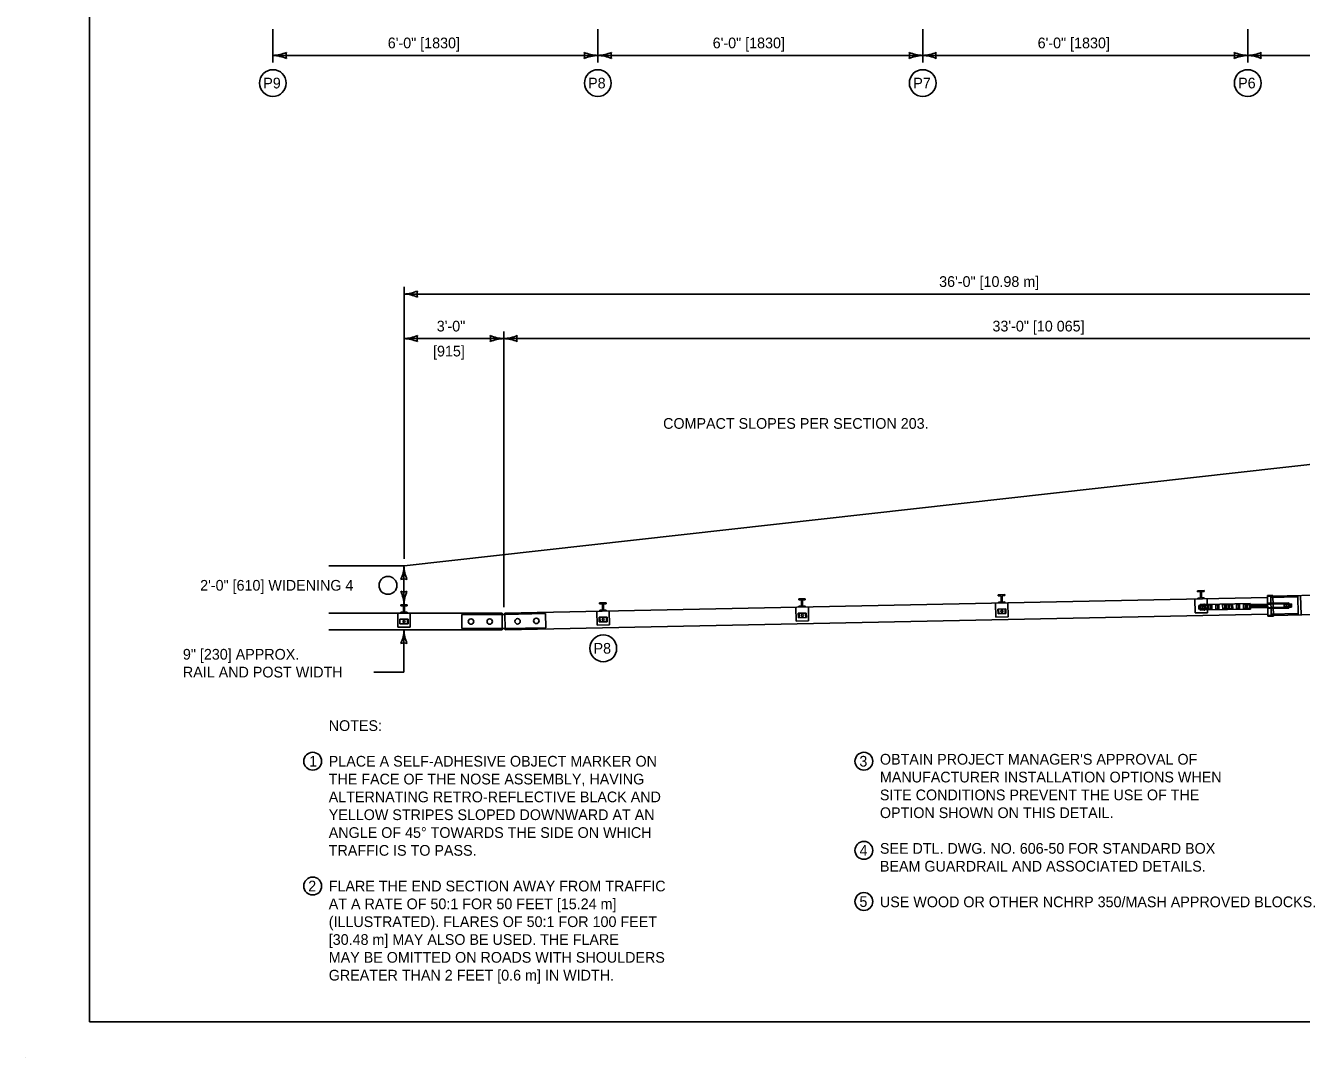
# Model space of a CAD drawing. Extents: x 49991.4 to 50021, y 49987.6 to 50011.4.
# Drawn here: x 49999.02 to 50006.18, y 49987.6 to 49993.39 of the extents above; entities that cross this region are included whole.
import ezdxf

# ---------------------------------------------------------------- set-up
doc = ezdxf.new("R2010")
doc.units = 0
for name, color, linetype in [('Level 1', 7, 'Continuous'), ('Level 2', 7, 'Continuous'), ('Level 3', 7, 'Continuous'), ('Level 4', 7, 'Continuous')]:
    doc.layers.add(name, color=color, linetype=linetype)

msp = doc.modelspace()

# ---------------------------------------------------------------- linework, layer by layer
at = {"layer": 'Level 1'}
for p, q in [((50007.8759, 49991.1095), (50001.1481, 49990.3564)), ((50001.1481, 49990.3564), (50000.7259, 49990.3564)), ((50010.3716, 49990.2756), (50006.023, 49990.1867)), ((50004.5183, 49990.1948), (50004.4821, 49990.1941)), ((50004.4821, 49990.1885), (50004.4821, 49990.1941)), ((50004.5184, 49990.1892), (50004.5183, 49990.1948)), ((50005.6363, 49990.2177), (50005.6001, 49990.217)), ((50005.6002, 49990.2114), (50005.6001, 49990.217)), ((50005.6155, 49990.2116), (50005.6002, 49990.2114)), ((50005.6162, 49990.1763), (50005.6155, 49990.2116)), ((50005.6364, 49990.2121), (50005.6211, 49990.2118)), ((50005.6218, 49990.1764), (50005.6211, 49990.2118)), ((50005.6364, 49990.2121), (50005.6363, 49990.2177)), ((50001.13, 49990.1317), (50001.13, 49990.1374)), ((50001.1662, 49990.1374), (50001.13, 49990.1374)), ((50001.1453, 49990.1317), (50001.13, 49990.1317)), ((50001.1453, 49990.0964), (50001.1453, 49990.1317)), ((50001.151, 49990.0964), (50001.151, 49990.1317)), ((50001.1662, 49990.1317), (50001.151, 49990.1317)), ((50001.1662, 49990.1317), (50001.1662, 49990.1374)), ((50005.992, 49990.1783), (50001.7142, 49990.0907)), ((50002.2817, 49990.149), (50002.2455, 49990.1483)), ((50002.2455, 49990.1426), (50002.2455, 49990.1483)), ((50002.2609, 49990.1429), (50002.2455, 49990.1426)), ((50002.2617, 49990.1076), (50002.2609, 49990.1429)), ((50002.2819, 49990.1433), (50002.2666, 49990.143)), ((50002.2673, 49990.1077), (50002.2666, 49990.143)), ((50002.2819, 49990.1433), (50002.2817, 49990.149)), ((50003.3986, 49990.1718), (50003.3623, 49990.1711)), ((50003.3624, 49990.1655), (50003.3623, 49990.1711)), ((50003.3778, 49990.1658), (50003.3624, 49990.1655)), ((50003.3785, 49990.1304), (50003.3631, 49990.1301)), ((50003.3632, 49990.1245), (50003.3631, 49990.1301)), ((50003.3785, 49990.1304), (50003.3778, 49990.1658)), ((50003.3987, 49990.1662), (50003.3833, 49990.1659)), ((50003.384, 49990.1305), (50003.3833, 49990.1659)), ((50003.3994, 49990.1308), (50003.384, 49990.1305)), ((50003.3987, 49990.1662), (50003.3986, 49990.1718)), ((50003.3995, 49990.1252), (50003.3994, 49990.1308)), ((50004.4974, 49990.1887), (50004.4821, 49990.1885)), ((50004.4982, 49990.1533), (50004.4829, 49990.153)), ((50004.4831, 49990.1474), (50004.4829, 49990.153)), ((50004.4982, 49990.1533), (50004.4974, 49990.1887)), ((50004.5184, 49990.1892), (50004.503, 49990.1888)), ((50004.5038, 49990.1535), (50004.503, 49990.1888)), ((50004.5191, 49990.1538), (50004.5038, 49990.1535)), ((50004.5192, 49990.1482), (50004.5191, 49990.1538)), ((50005.6162, 49990.1763), (50005.6009, 49990.1759)), ((50005.6011, 49990.1703), (50005.6009, 49990.1759)), ((50005.6371, 49990.1767), (50005.6218, 49990.1764)), ((50005.6372, 49990.1711), (50005.6371, 49990.1767)), ((50006.0229, 49990.1907), (50005.9918, 49990.1901)), ((50005.9942, 49990.0736), (50005.9918, 49990.1901)), ((50006.0253, 49990.0742), (50006.0229, 49990.1907)), ((50001.6988, 49990.0908), (50000.7259, 49990.0908)), ((50001.1249, 49990.0578), (50001.1249, 49990.0306)), ((50001.1714, 49990.0578), (50001.1249, 49990.0578)), ((50001.1453, 49990.0964), (50001.13, 49990.0964)), ((50001.13, 49990.0908), (50001.13, 49990.0964)), ((50001.1662, 49990.0964), (50001.151, 49990.0964)), ((50001.1662, 49990.0908), (50001.1662, 49990.0964)), ((50001.1677, 49990.0578), (50001.1677, 49990.0306)), ((50001.1714, 49990.0578), (50001.1714, 49990.0306)), ((50001.6988, 49990.0907), (50001.6988, 49989.9976)), ((50001.7143, 49990.0838), (50001.6988, 49990.0838)), ((50001.7142, 49990.0907), (50001.7161, 49989.9975)), ((50002.243, 49990.0679), (50002.2878, 49990.0688)), ((50002.2878, 49990.0688), (50002.243, 49990.0679)), ((50002.2435, 49990.0421), (50002.243, 49990.0679)), ((50002.2435, 49990.0421), (50002.243, 49990.0679)), ((50002.2617, 49990.1076), (50002.2463, 49990.1072)), ((50002.2464, 49990.1016), (50002.2463, 49990.1072)), ((50002.2837, 49990.0688), (50002.2471, 49990.068)), ((50002.2471, 49990.068), (50002.2476, 49990.0422)), ((50002.2471, 49990.068), (50002.2476, 49990.0422)), ((50002.2826, 49990.1081), (50002.2673, 49990.1077)), ((50002.2827, 49990.1025), (50002.2826, 49990.1081)), ((50002.2842, 49990.0429), (50002.2837, 49990.0688)), ((50002.2842, 49990.0429), (50002.2837, 49990.0688)), ((50002.2878, 49990.0688), (50002.2883, 49990.043)), ((50002.2883, 49990.043), (50002.2878, 49990.0688)), ((50003.3601, 49990.0908), (50003.4049, 49990.0917)), ((50003.3606, 49990.0649), (50003.3601, 49990.0908)), ((50003.3606, 49990.0649), (50003.4054, 49990.0658)), ((50003.3642, 49990.0908), (50003.3647, 49990.065)), ((50003.4008, 49990.0916), (50003.4013, 49990.0657)), ((50003.4054, 49990.0658), (50003.4049, 49990.0917)), ((50004.4798, 49990.1137), (50004.5246, 49990.1146)), ((50004.4804, 49990.0879), (50004.4798, 49990.1137)), ((50004.4804, 49990.0879), (50004.5251, 49990.0888)), ((50004.4839, 49990.1138), (50004.4844, 49990.088)), ((50004.5205, 49990.1145), (50004.521, 49990.0887)), ((50004.5251, 49990.0888), (50004.5246, 49990.1146)), ((50006.0253, 49990.0742), (50005.9942, 49990.0736)), ((50006.7216, 49990.0924), (50006.0252, 49990.078)), ((50001.6988, 49989.9976), (50000.7259, 49989.9976)), ((50001.1714, 49990.0306), (50001.1249, 49990.0306)), ((50001.716, 49990.0044), (50001.6988, 49990.0044)), ((50002.2883, 49990.043), (50002.2435, 49990.0421)), ((50002.2435, 49990.0421), (50002.2883, 49990.043)), ((49999.0245, 49987.5988), (49999.0245, 49987.5988))]:
    msp.add_line(p, q, dxfattribs=at)
msp.add_lwpolyline([(49999.3835, 49998.9992), (50016.7501, 49998.9992), (50016.7501, 49987.7988), (49999.3835, 49987.7988)], close=True, dxfattribs=at)
msp.add_lwpolyline([(50001.7161, 49989.9975), (50005.994, 49990.0852)], dxfattribs=at)
for centre, radius in [((50001.1482, 49990.0442), 0.00582), ((50001.524, 49990.0441), 0.0153), ((50001.6288, 49990.0441), 0.0153), ((50001.7852, 49990.0455), 0.0153), ((50001.89, 49990.0477), 0.0153), ((50002.2656, 49990.0555), 0.00582), ((50003.3827, 49990.0783), 0.00582), ((50004.5025, 49990.1012), 0.00582)]:
    msp.add_circle(centre, radius, dxfattribs=at)
at = {"layer": 'Level 2'}
for centre, radius in [((50000.4122, 49993.0644), 0.075), ((50002.2352, 49993.0644), 0.075), ((50004.0582, 49993.0644), 0.075), ((50005.8814, 49993.0644), 0.075), ((50001.0578, 49990.2469), 0.05), ((50002.2658, 49989.8938), 0.075), ((50000.6357, 49989.2604), 0.05), ((50003.7279, 49989.2604), 0.05), ((50003.7279, 49988.7604), 0.05), ((50000.6357, 49988.5604), 0.05), ((50003.7279, 49988.4735), 0.05)]:
    msp.add_circle(centre, radius, dxfattribs=at)
at = {"layer": 'Level 3'}
for p, q in [((50000.4122, 49993.3671), (50000.4122, 49993.1794)), ((50002.2352, 49993.3671), (50002.2352, 49993.1794)), ((50004.0582, 49993.3671), (50004.0582, 49993.1794)), ((50005.8814, 49993.3671), (50005.8814, 49993.1794)), ((50002.2358, 49993.2194), (50000.4128, 49993.2194)), ((50004.0588, 49993.2194), (50002.2358, 49993.2194)), ((50005.8818, 49993.2194), (50004.0588, 49993.2194)), ((50007.7048, 49993.2194), (50005.8818, 49993.2194)), ((50001.1481, 49990.3964), (50001.1481, 49991.921)), ((50007.8759, 49991.881), (50001.1481, 49991.881)), ((50001.7075, 49991.631), (50001.1481, 49991.631)), ((50001.7075, 49990.1238), (50001.7075, 49991.671)), ((50007.8759, 49991.631), (50001.7075, 49991.631)), ((50001.1478, 49990.1374), (50001.1478, 49990.3564)), ((50001.1478, 49989.7604), (50001.1478, 49989.9976)), ((50000.978, 49989.7604), (50001.1478, 49989.7604))]:
    msp.add_line(p, q, dxfattribs=at)
for centre, radius, start, end in [((50000.4007, 49993.4521), 0.233, 272.82731, 292.07716), ((50000.403, 49992.9972), 0.2223, 67.45601, 87.63952), ((50000.5404, 49993.2194), 0.0548, 162.13882, 197.86118), ((50002.2444, 49993.4415), 0.2223, 247.45601, 267.63952), ((50002.107, 49993.2194), 0.0548, 342.13882, 17.86118), ((50002.2467, 49992.9867), 0.233, 92.82731, 112.07716), ((50002.2237, 49993.4521), 0.233, 272.82731, 292.07716), ((50002.226, 49992.9973), 0.2223, 67.45601, 87.63952), ((50002.3634, 49993.2194), 0.0548, 162.13882, 197.86118), ((50004.0674, 49993.4415), 0.2223, 247.45601, 267.63952), ((50003.93, 49993.2194), 0.0548, 342.13882, 17.86118), ((50004.0697, 49992.9867), 0.233, 92.82731, 112.07716), ((50004.0467, 49993.4521), 0.233, 272.82731, 292.07716), ((50004.049, 49992.9973), 0.2223, 67.45601, 87.63952), ((50004.1864, 49993.2194), 0.0548, 162.13882, 197.86118), ((50005.8906, 49993.4415), 0.2223, 247.45601, 267.63952), ((50005.7532, 49993.2194), 0.0548, 342.13882, 17.86118), ((50005.8929, 49992.9867), 0.233, 92.82731, 112.07716), ((50005.8699, 49993.4521), 0.233, 272.82731, 292.07716), ((50005.8722, 49992.9973), 0.2223, 67.45601, 87.63952), ((50006.0096, 49993.2194), 0.0548, 162.13882, 197.86118), ((50001.1366, 49992.1137), 0.233, 272.82731, 292.07716), ((50001.1389, 49991.6589), 0.2223, 67.45601, 87.63952), ((50001.2763, 49991.881), 0.0548, 162.13882, 197.86118), ((50001.1366, 49991.8637), 0.233, 272.82731, 292.07716), ((50001.1389, 49991.4089), 0.2223, 67.45601, 87.63952), ((50001.2763, 49991.631), 0.0548, 162.13882, 197.86118), ((50001.7167, 49991.8531), 0.2223, 247.45601, 267.63952), ((50001.5793, 49991.631), 0.0548, 342.13882, 17.86118), ((50001.719, 49991.3983), 0.233, 92.82731, 112.07716), ((50001.696, 49991.8637), 0.233, 272.82731, 292.07716), ((50001.6983, 49991.4089), 0.2223, 67.45601, 87.63952), ((50001.8357, 49991.631), 0.0548, 162.13882, 197.86118), ((50000.9257, 49990.3656), 0.2223, 337.45601, 357.63952), ((50001.3805, 49990.3679), 0.233, 182.82731, 202.07716), ((50001.1478, 49990.2282), 0.0548, 72.13882, 107.86118), ((50001.1478, 49990.2656), 0.0548, 252.13882, 287.86118), ((50000.9151, 49990.1259), 0.233, 2.82731, 22.07716), ((50001.3699, 49990.1282), 0.2223, 157.45601, 177.63952), ((50000.9257, 49990.0068), 0.2223, 337.45601, 357.63952), ((50001.3805, 49990.0091), 0.233, 182.82731, 202.07716), ((50001.1478, 49989.8694), 0.0548, 72.13882, 107.86118)]:
    msp.add_arc(centre, radius, start, end, dxfattribs=at)
at = {"layer": 'Level 4'}
for p, q in [((50003.348, 49990.0465), (50003.3465, 49990.1241)), ((50003.4181, 49990.0479), (50003.4164, 49990.1255)), ((50004.4677, 49990.0694), (50004.4661, 49990.1471)), ((50004.5376, 49990.0708), (50004.536, 49990.1485)), ((50005.5857, 49990.0923), (50005.5842, 49990.17)), ((50005.6062, 49990.1335), (50005.6396, 49990.1341)), ((50005.6066, 49990.1142), (50005.6062, 49990.1335)), ((50005.6105, 49990.1197), (50005.6103, 49990.128)), ((50005.6138, 49990.1396), (50005.6356, 49990.14)), ((50005.6145, 49990.1085), (50005.6138, 49990.1396)), ((50005.614, 49990.1312), (50005.6358, 49990.1316)), ((50005.6254, 49990.1088), (50005.6248, 49990.1398)), ((50005.6394, 49990.142), (50005.6356, 49990.142)), ((50005.6363, 49990.1071), (50005.6356, 49990.142)), ((50005.8956, 49990.1453), (50005.6394, 49990.14)), ((50005.6401, 49990.1071), (50005.6394, 49990.142)), ((50005.6569, 49990.1366), (50005.6453, 49990.1364)), ((50005.6459, 49990.113), (50005.6453, 49990.1364)), ((50005.6558, 49990.0937), (50005.6541, 49990.1714)), ((50005.6575, 49990.1133), (50005.6569, 49990.1366)), ((50005.6803, 49990.137), (50005.6628, 49990.1367)), ((50005.6633, 49990.1134), (50005.6628, 49990.1367)), ((50005.6748, 49990.1137), (50005.6744, 49990.1369)), ((50005.6807, 49990.1138), (50005.6803, 49990.137)), ((50005.719, 49990.1379), (50005.7015, 49990.1375)), ((50005.702, 49990.1143), (50005.7015, 49990.1375)), ((50005.7137, 49990.1145), (50005.7132, 49990.1378)), ((50005.7195, 49990.1146), (50005.719, 49990.1379)), ((50005.758, 49990.1387), (50005.7405, 49990.1383)), ((50005.741, 49990.115), (50005.7405, 49990.1383)), ((50005.7526, 49990.1152), (50005.7521, 49990.1386)), ((50005.7585, 49990.1153), (50005.758, 49990.1387)), ((50005.7735, 49990.139), (50005.7619, 49990.1388)), ((50005.7624, 49990.1155), (50005.7619, 49990.1388)), ((50005.774, 49990.1157), (50005.7735, 49990.139)), ((50005.7968, 49990.1393), (50005.7793, 49990.1391)), ((50005.7798, 49990.1158), (50005.7793, 49990.1391)), ((50005.7914, 49990.1161), (50005.791, 49990.1392)), ((50005.7972, 49990.1162), (50005.7968, 49990.1393)), ((50005.8355, 49990.1402), (50005.818, 49990.1399)), ((50005.8185, 49990.1166), (50005.818, 49990.1399)), ((50005.8301, 49990.1168), (50005.8296, 49990.1401)), ((50005.836, 49990.1169), (50005.8355, 49990.1402)), ((50005.8743, 49990.141), (50005.8569, 49990.1407)), ((50005.8574, 49990.1174), (50005.8569, 49990.1407)), ((50005.8689, 49990.1175), (50005.8685, 49990.1409)), ((50005.8748, 49990.1176), (50005.8743, 49990.141)), ((50005.8899, 49990.1413), (50005.8783, 49990.1412)), ((50005.8787, 49990.1179), (50005.8783, 49990.1412)), ((50005.8905, 49990.1181), (50005.8899, 49990.1413)), ((50005.8963, 49990.1143), (50005.8956, 49990.1453)), ((50005.8957, 49990.1395), (50006.1271, 49990.1442)), ((50006.1275, 49990.1248), (50005.8962, 49990.1201)), ((50005.8999, 49990.1258), (50005.8998, 49990.134)), ((50005.9039, 49990.1202), (50005.9034, 49990.1396)), ((50005.9077, 49990.1258), (50005.9076, 49990.1341)), ((50005.9117, 49990.1205), (50005.9112, 49990.1398)), ((50005.9154, 49990.1261), (50005.9153, 49990.1343)), ((50005.9194, 49990.1206), (50005.919, 49990.14)), ((50005.9231, 49990.1262), (50005.923, 49990.1344)), ((50005.9273, 49990.1207), (50005.9269, 49990.1401)), ((50005.9311, 49990.1263), (50005.931, 49990.1346)), ((50005.935, 49990.1209), (50005.9346, 49990.1403)), ((50005.9388, 49990.1266), (50005.9387, 49990.1348)), ((50005.9427, 49990.1211), (50005.9423, 49990.1404)), ((50005.9466, 49990.1266), (50005.9464, 49990.1349)), ((50005.9505, 49990.1212), (50005.9501, 49990.1406)), ((50005.9544, 49990.1268), (50005.9541, 49990.1351)), ((50005.9583, 49990.1214), (50005.958, 49990.1408)), ((50005.9622, 49990.1271), (50005.9619, 49990.1353)), ((50005.966, 49990.1215), (50005.9657, 49990.1409)), ((50005.9699, 49990.1272), (50005.9696, 49990.1354)), ((50005.9738, 49990.1217), (50005.9735, 49990.141)), ((50005.9778, 49990.1273), (50005.9775, 49990.1355)), ((50005.9816, 49990.1219), (50005.9813, 49990.1413)), ((50005.9855, 49990.1274), (50005.9853, 49990.1357)), ((50005.9895, 49990.122), (50005.9892, 49990.1414)), ((50006.023, 49990.1867), (50005.9919, 49990.1861)), ((50005.9927, 49990.1474), (50006.1115, 49990.1497)), ((50006.0137, 49990.0779), (50006.0115, 49990.1864)), ((50006.1629, 49990.1819), (50006.0117, 49990.1786)), ((50006.0864, 49990.1183), (50006.0858, 49990.1492)), ((50006.0904, 49990.1183), (50006.0898, 49990.1493)), ((50006.09, 49990.1408), (50006.1117, 49990.1412)), ((50006.1119, 49990.1272), (50006.0902, 49990.1266)), ((50006.1012, 49990.1186), (50006.1006, 49990.1495)), ((50006.1121, 49990.1188), (50006.1115, 49990.1497)), ((50006.1156, 49990.1302), (50006.1154, 49990.1384)), ((50006.1198, 49990.1246), (50006.1195, 49990.144)), ((50006.1236, 49990.1302), (50006.1234, 49990.1385)), ((50006.1275, 49990.1248), (50006.1271, 49990.1442)), ((50006.165, 49990.0809), (50006.1627, 49990.1896)), ((50006.1806, 49990.0812), (50006.1783, 49990.1899)), ((50001.1131, 49990.013), (50001.1131, 49990.0908)), ((50001.183, 49990.013), (50001.183, 49990.0908)), ((50001.4715, 49990.0044), (50001.4715, 49990.0838)), ((50001.4715, 49990.0838), (50001.6988, 49990.0838)), ((50001.9416, 49990.0885), (50001.7143, 49990.0838)), ((50001.9432, 49990.009), (50001.9416, 49990.0885)), ((50002.2312, 49990.0235), (50002.2295, 49990.1013)), ((50002.301, 49990.0249), (50002.2995, 49990.1028)), ((50004.5376, 49990.0708), (50004.4677, 49990.0694)), ((50005.6558, 49990.0937), (50005.5857, 49990.0923)), ((50005.6399, 49990.1147), (50005.6066, 49990.1141)), ((50005.6361, 49990.1174), (50005.6143, 49990.1169)), ((50005.6362, 49990.109), (50005.6145, 49990.1085)), ((50005.6401, 49990.1071), (50005.6363, 49990.1071)), ((50005.8963, 49990.1143), (50005.64, 49990.1091)), ((50005.6575, 49990.1133), (50005.6459, 49990.113)), ((50005.6807, 49990.1138), (50005.6633, 49990.1134)), ((50005.7195, 49990.1146), (50005.702, 49990.1143)), ((50005.7585, 49990.1153), (50005.741, 49990.115)), ((50005.774, 49990.1157), (50005.7624, 49990.1155)), ((50005.7972, 49990.1162), (50005.7798, 49990.1158)), ((50005.836, 49990.1169), (50005.8185, 49990.1166)), ((50005.8748, 49990.1176), (50005.8574, 49990.1174)), ((50005.8905, 49990.1181), (50005.8787, 49990.1179)), ((50006.1121, 49990.1188), (50005.9933, 49990.1163)), ((50006.0252, 49990.078), (50005.9941, 49990.0775)), ((50006.1648, 49990.0888), (50006.0135, 49990.0856)), ((50001.183, 49990.013), (50001.1131, 49990.013)), ((50001.4715, 49990.0044), (50001.6988, 49990.0044)), ((50001.9432, 49990.009), (50001.716, 49990.0044)), ((50002.301, 49990.0249), (50002.2312, 49990.0235)), ((50003.4181, 49990.0479), (50003.348, 49990.0465))]:
    msp.add_line(p, q, dxfattribs=at)

# ---------------------------------------------------------------- texts
at = {"layer": 'Level 1'}
msp.add_text('6\'-0" [1830]', height=0.06, dxfattribs=at).set_placement((50001.0568, 49993.2594))
at = {"layer": 'Level 2'}
for s, p in [('6\'-0" [1830]', (50002.8798, 49993.2594)), ('6\'-0" [1830]', (50004.7028, 49993.2594)), ('P9', (50000.3583, 49993.0344)), ('P8', (50002.1808, 49993.0344)), ('P7', (50004.005, 49993.0344)), ('P6', (50005.8275, 49993.0344)), ('36\'-0" [10.98 m]', (50004.1502, 49991.921)), ('3\'-0"', (50001.3317, 49991.671)), ('33\'-0" [10 065]', (50004.4493, 49991.671)), ('[915]', (50001.3107, 49991.531)), ('COMPACT SLOPES PER SECTION 203.', (50002.6016, 49991.1251)), ('2\'-0" [610] WIDENING 4', (50000.0042, 49990.2172)), ('P8', (50002.2114, 49989.8638)), ('9" [230] APPROX.', (49999.9075, 49989.8304)), ('RAIL AND POST WIDTH', (49999.9075, 49989.7304)), ('NOTES:', (50000.7257, 49989.4304)), ('1', (50000.6159, 49989.2304)), ('PLACE A SELF-ADHESIVE OBJECT MARKER ON', (50000.7257, 49989.2304)), ('3', (50003.7027, 49989.2304)), ("OBTAIN PROJECT MANAGER'S APPROVAL OF ", (50003.8179, 49989.2416)), ('THE FACE OF THE NOSE ASSEMBLY, HAVING', (50000.7257, 49989.1304)), ('MANUFACTURER INSTALLATION OPTIONS WHEN ', (50003.8179, 49989.1416)), ('ALTERNATING RETRO-REFLECTIVE BLACK AND', (50000.7257, 49989.0304)), ('SITE CONDITIONS PREVENT THE USE OF THE ', (50003.8179, 49989.0416)), ('YELLOW STRIPES SLOPED DOWNWARD AT AN', (50000.7257, 49988.9304)), ('OPTION SHOWN ON THIS DETAIL.', (50003.8179, 49988.9416)), ('ANGLE OF 45° TOWARDS THE SIDE ON WHICH', (50000.7257, 49988.8304)), ('TRAFFIC IS TO PASS.', (50000.7257, 49988.7304)), ('4', (50003.7039, 49988.7304)), ('SEE DTL. DWG. NO. 606-50 FOR STANDARD BOX ', (50003.8179, 49988.7416)), ('BEAM GUARDRAIL AND ASSOCIATED DETAILS.', (50003.8179, 49988.6416)), ('2', (50000.6105, 49988.5304)), ('FLARE THE END SECTION AWAY FROM TRAFFIC', (50000.7257, 49988.5304)), ('AT A RATE OF 50:1 FOR 50 FEET [15.24 m]', (50000.7257, 49988.4304)), ('5', (50003.703, 49988.4435)), ('USE WOOD OR OTHER NCHRP 350/MASH APPROVED BLOCKS.', (50003.8179, 49988.4416)), ('(ILLUSTRATED). FLARES OF 50:1 FOR 100 FEET', (50000.7257, 49988.3304)), ('[30.48 m] MAY ALSO BE USED. THE FLARE', (50000.7257, 49988.2304)), ('MAY BE OMITTED ON ROADS WITH SHOULDERS', (50000.7257, 49988.1304)), ('GREATER THAN 2 FEET [0.6 m] IN WIDTH.', (50000.7257, 49988.0304))]:
    msp.add_text(s, height=0.06, dxfattribs=at).set_placement(p)

doc.saveas('drawing.dxf')
